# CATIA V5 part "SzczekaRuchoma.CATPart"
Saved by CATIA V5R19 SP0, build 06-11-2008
Part number: Szczęka ruchoma
Bounding box of the stored display mesh (mm): x -75.565 to 75.565, y 66.929 to 122.377, z -229.297 to -102.297
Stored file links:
  D:\POBO\catia\test\Imadło\SzczekaRuchoma.CATPart
  E:\Podręcznik\catia\symulacja\SW3dPS-49472SC.CATPART
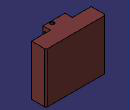
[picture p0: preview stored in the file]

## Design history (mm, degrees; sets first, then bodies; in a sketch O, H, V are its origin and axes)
Body1 (main body)
  Solid1 "Manifold Solid #24701": solid without history
  Chamfer1: length 4, angle 45, on edge [face of Solid1 | face of Solid1]
  Chamfer2: length 4, angle 45, on edge [face of Solid1 | face of Solid1]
